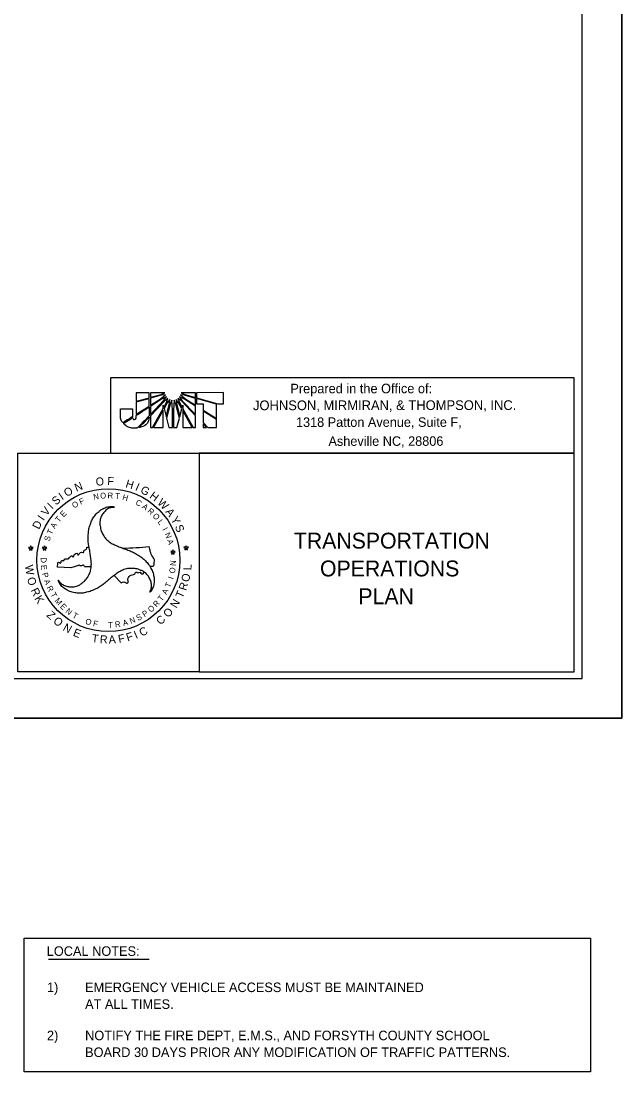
# Model space of a CAD drawing. Extents: x 762655 to 770567, y 650864 to 655190.
# Drawn here: x 765831 to 766209, y 652556 to 653217 of the extents above; entities that cross this region are included whole.
import ezdxf

# ---------------------------------------------------------------- set-up
doc = ezdxf.new("R2010")
doc.units = 0
for name, color, linetype in [('Default', 7, 'Continuous'), ('DEV BORDER CELL', 7, 'Continuous'), ('DEV DOT SWIRL SEAL CELL', 7, 'Continuous'), ('Scratch_Level_3', 7, 'Continuous'), ('Sheet Plan CELL', 7, 'Continuous'), ('Sheet Plot Border Outside CELL', 7, 'Continuous'), ('Sheet Title CELL', 7, 'Continuous'), ('Text', 7, 'Continuous')]:
    doc.layers.add(name, color=color, linetype=linetype)

msp = doc.modelspace()

# ---------------------------------------------------------------- linework, layer by layer
at = {"layer": 'Default'}
for p, q in [((765911.27, 652983.54), (765903.17, 652983.54)), ((765903.17, 652983.54), (765903.17, 652978.17)), ((765911.27, 652980.42), (765911.27, 652983.54)), ((765921.22, 652983.59), (765912.11, 652983.59)), ((765912.11, 652983.59), (765912.11, 652980.69)), ((765918.9, 652982.56), (765921.22, 652983.59)), ((765940.51, 652983.57), (765931.53, 652983.6)), ((765931.53, 652983.6), (765933.81, 652982.54)), ((765940.51, 652980.66), (765940.51, 652983.57)), ((765958.16, 652983.63), (765941.14, 652983.61)), ((765941.14, 652983.61), (765941.14, 652980.49)), ((765958.17, 652976.65), (765958.16, 652983.63)), ((765903.17, 652978.17), (765911.27, 652980.42)), ((765911.27, 652979.83), (765903.18, 652977.55)), ((765903.18, 652977.55), (765903.18, 652970)), ((765911.27, 652975.14), (765911.27, 652979.83)), ((765912.11, 652980.69), (765918.9, 652982.56)), ((765918.9, 652981.94), (765912.11, 652980.06)), ((765912.11, 652980.06), (765912.11, 652975.68)), ((765912.11, 652975.68), (765918.19, 652979.53)), ((765919.13, 652979.44), (765912.12, 652974.97)), ((765912.12, 652969.92), (765920.65, 652978.81)), ((765921, 652978.37), (765912.12, 652969.06)), ((765918.19, 652979.53), (765921.54, 652982.26)), ((765921.54, 652982.26), (765918.9, 652981.94)), ((765922.21, 652981), (765919.13, 652979.44)), ((765920.47, 652974.35), (765922.16, 652977.44)), ((765920.65, 652978.81), (765922.21, 652981)), ((765922.71, 652977.25), (765920.69, 652973.59)), ((765923.15, 652980.03), (765921, 652978.37)), ((765921.99, 652968.72), (765924.08, 652976.81)), ((765922.16, 652977.44), (765923.15, 652980.03)), ((765924.31, 652979.31), (765922.71, 652977.25)), ((765924.08, 652976.81), (765924.31, 652979.31)), ((765925.65, 652978.95), (765924.54, 652976.36)), ((765926, 652972.56), (765925.65, 652978.95)), ((765926.98, 652978.95), (765926.57, 652972.56)), ((765928.05, 652976.36), (765926.98, 652978.95)), ((765928.28, 652979.31), (765928.55, 652976.72)), ((765929.84, 652977.26), (765928.28, 652979.31)), ((765929.43, 652980.03), (765930.42, 652977.44)), ((765931.58, 652978.38), (765929.43, 652980.03)), ((765931.94, 652973.46), (765929.84, 652977.26)), ((765930.37, 652981.01), (765931.94, 652978.78)), ((765933.5, 652979.45), (765930.37, 652981.01)), ((765930.42, 652977.44), (765932.16, 652974.22)), ((765931.08, 652982.27), (765934.48, 652979.49)), ((765933.58, 652981.95), (765931.08, 652982.27)), ((765940.47, 652969.01), (765931.58, 652978.38)), ((765931.94, 652978.78), (765940.47, 652969.85)), ((765940.47, 652975.03), (765933.5, 652979.45)), ((765940.51, 652980.04), (765933.58, 652981.95)), ((765933.81, 652982.54), (765940.51, 652980.66)), ((765934.48, 652979.49), (765940.47, 652975.76)), ((765940.47, 652975.76), (765940.51, 652980.04)), ((765941.14, 652980.49), (765941.14, 652980.39)), ((765941.14, 652980.39), (765954.55, 652976.65)), ((765941.14, 652979.91), (765941.14, 652979.86)), ((765953.69, 652976.34), (765941.14, 652979.91)), ((765941.14, 652979.86), (765941.15, 652976.6)), ((765903.18, 652970), (765911.27, 652975.14)), ((765912.12, 652974.97), (765912.12, 652969.92)), ((765913.46, 652961.72), (765920.07, 652973.68)), ((765920.07, 652972.52), (765914.09, 652961.72)), ((765920.07, 652973.68), (765920.06, 652975.82)), ((765920.06, 652975.82), (765920.47, 652974.35)), ((765920.13, 652961.72), (765920.07, 652972.52)), ((765920.69, 652973.59), (765921.99, 652968.72)), ((765924.54, 652976.36), (765922.26, 652967.6)), ((765926.01, 652961.77), (765926, 652972.56)), ((765926.57, 652972.56), (765926.58, 652961.77)), ((765930.39, 652967.48), (765928.05, 652976.36)), ((765928.55, 652976.72), (765930.65, 652968.55)), ((765930.65, 652968.55), (765931.94, 652973.46)), ((765932.16, 652974.22), (765932.57, 652975.83)), ((765932.57, 652975.83), (765932.57, 652973.46)), ((765932.57, 652973.46), (765939.05, 652961.74)), ((765938.38, 652961.78), (765932.57, 652972.3)), ((765932.57, 652972.3), (765932.58, 652961.77)), ((765940.47, 652969.85), (765940.47, 652975.03)), ((765941.15, 652976.6), (765945.3, 652976.6)), ((765945.3, 652976.6), (765945.3, 652972.71)), ((765945.3, 652972.71), (765953.7, 652967.4)), ((765945.31, 652972.05), (765945.31, 652964.8)), ((765953.7, 652966.78), (765945.31, 652972.05)), ((765953.7, 652967.4), (765953.69, 652976.34)), ((765954.55, 652976.65), (765958.17, 652976.65)), ((765912.12, 652969.06), (765912.13, 652961.72)), ((765922.26, 652967.6), (765923.79, 652961.77)), ((765928.83, 652961.77), (765930.39, 652967.48)), ((765940.48, 652961.74), (765940.47, 652969.01)), ((765945.31, 652964.8), (765948.21, 652961.75)), ((765947.41, 652961.75), (765945.31, 652964.02)), ((765945.31, 652964.02), (765945.31, 652961.75)), ((765953.7, 652961.75), (765953.7, 652966.78)), ((765912.13, 652961.72), (765913.46, 652961.72)), ((765914.09, 652961.72), (765920.13, 652961.72)), ((765923.79, 652961.77), (765926.01, 652961.77)), ((765926.58, 652961.77), (765928.83, 652961.77)), ((765932.58, 652961.77), (765938.38, 652961.78)), ((765939.05, 652961.74), (765940.48, 652961.74)), ((765945.31, 652961.75), (765947.41, 652961.75)), ((765948.21, 652961.75), (765953.7, 652961.75)), ((765847.91, 652627.18), (765911.34, 652627.18))]:
    msp.add_line(p, q, dxfattribs=at)
for points in [[(765903.17, 652978.17), (765911.27, 652980.42), (765911.27, 652983.54), (765903.17, 652983.54), (765903.17, 652978.17)], [(765918.9, 652982.56), (765921.22, 652983.59), (765912.11, 652983.59), (765912.11, 652980.69), (765918.9, 652982.56)], [(765933.81, 652982.54), (765940.51, 652980.66), (765940.51, 652983.57), (765931.53, 652983.6), (765933.81, 652982.54)], [(765903.18, 652970), (765911.27, 652975.14), (765911.27, 652979.83), (765903.18, 652977.55), (765903.18, 652970)], [(765912.11, 652980.06), (765912.11, 652975.68), (765918.19, 652979.53), (765921.54, 652982.26), (765918.9, 652981.94), (765912.11, 652980.06)], [(765912.12, 652974.97), (765912.12, 652969.92), (765920.65, 652978.81), (765922.21, 652981), (765919.13, 652979.44), (765912.12, 652974.97)], [(765923.15, 652980.03), (765921, 652978.37), (765912.12, 652969.06), (765912.13, 652961.72), (765913.46, 652961.72), (765920.07, 652973.68), (765920.06, 652975.82), (765920.47, 652974.35), (765922.16, 652977.44), (765923.15, 652980.03)], [(765924.31, 652979.31), (765922.71, 652977.25), (765920.69, 652973.59), (765921.99, 652968.72), (765924.08, 652976.81), (765924.31, 652979.31)], [(765924.54, 652976.36), (765922.26, 652967.6), (765923.79, 652961.77), (765926.01, 652961.77), (765926, 652972.56), (765925.65, 652978.95), (765924.54, 652976.36)], [(765926.98, 652978.95), (765926.57, 652972.56), (765926.58, 652961.77), (765928.83, 652961.77), (765930.39, 652967.48), (765928.05, 652976.36), (765926.98, 652978.95)], [(765928.28, 652979.31), (765928.55, 652976.72), (765930.65, 652968.55), (765931.94, 652973.46), (765929.84, 652977.26), (765928.28, 652979.31)], [(765929.43, 652980.03), (765930.42, 652977.44), (765932.16, 652974.22), (765932.57, 652975.83), (765932.57, 652973.46), (765939.05, 652961.74), (765940.48, 652961.74), (765940.47, 652969.01), (765931.58, 652978.38), (765929.43, 652980.03)], [(765930.37, 652981.01), (765931.94, 652978.78), (765940.47, 652969.85), (765940.47, 652975.03), (765933.5, 652979.45), (765930.37, 652981.01)], [(765931.08, 652982.27), (765934.48, 652979.49), (765940.47, 652975.76), (765940.51, 652980.04), (765933.58, 652981.95), (765931.08, 652982.27)], [(765941.14, 652979.91), (765941.14, 652979.86), (765941.15, 652976.6), (765945.3, 652976.6), (765945.3, 652972.71), (765953.7, 652967.4), (765953.69, 652976.34), (765941.14, 652979.91)], [(765914.09, 652961.72), (765920.13, 652961.72), (765920.07, 652972.52), (765914.09, 652961.72)], [(765932.58, 652961.77), (765938.38, 652961.78), (765932.57, 652972.3), (765932.58, 652961.77)], [(765945.31, 652972.05), (765945.31, 652964.8), (765948.21, 652961.75), (765953.7, 652961.75), (765953.7, 652966.78), (765945.31, 652972.05), (765945.31, 652972.05)], [(765945.31, 652961.75), (765945.31, 652961.75), (765947.41, 652961.75), (765945.31, 652964.02), (765945.31, 652961.75)]]:
    msp.add_lwpolyline(points, dxfattribs=at)
for points in [[(765900.85, 652973.48), (765900.85, 652973.48), (765893.36, 652973.47), (765893.36, 652973.47), (765893.36, 652973.47), (765893.36, 652968.78), (765893.36, 652968.78), (765893.36, 652968.78), (765893.36, 652968.28), (765893.36, 652968.28), (765893.37, 652966.82), (765893.85, 652965.65), (765894.7, 652964.68), (765894.7, 652964.68), (765900.86, 652968.43), (765900.86, 652968.52), (765900.86, 652968.52), (765900.85, 652973.48), (765900.85, 652973.48)], [(765900.85, 652973.48), (765900.85, 652973.48), (765893.36, 652973.47), (765893.36, 652973.47), (765893.36, 652973.47), (765893.36, 652968.78), (765893.36, 652968.78), (765893.36, 652968.78), (765893.36, 652968.28), (765893.36, 652968.28), (765893.37, 652966.82), (765893.85, 652965.65), (765894.7, 652964.68), (765894.7, 652964.68), (765900.86, 652968.43), (765900.86, 652968.52), (765900.86, 652968.52), (765900.85, 652973.48), (765900.85, 652973.48)], [(765902.02, 652966.73), (765901.54, 652966.73), (765901.13, 652967), (765900.95, 652967.89), (765900.95, 652967.89), (765895.14, 652964.29), (765895.14, 652964.29), (765896.94, 652962.41), (765899.8, 652961.29), (765902.21, 652961.29), (765902.84, 652961.29), (765903.32, 652961.35), (765903.99, 652961.48), (765903.99, 652961.48), (765911.28, 652969.02), (765911.28, 652969.02), (765911.28, 652969.02), (765911.27, 652974.47), (765911.27, 652974.47), (765911.27, 652974.47), (765903.18, 652969.32), (765903.18, 652969.32), (765903.18, 652967.28), (765902.69, 652966.73), (765902.02, 652966.73)], [(765902.02, 652966.73), (765901.54, 652966.73), (765901.13, 652967), (765900.95, 652967.89), (765900.95, 652967.89), (765895.14, 652964.29), (765895.14, 652964.29), (765896.94, 652962.41), (765899.8, 652961.29), (765902.21, 652961.29), (765902.84, 652961.29), (765903.32, 652961.35), (765903.99, 652961.48), (765903.99, 652961.48), (765911.28, 652969.02), (765911.28, 652969.02), (765911.28, 652969.02), (765911.27, 652974.47), (765911.27, 652974.47), (765911.27, 652974.47), (765903.18, 652969.32), (765903.18, 652969.32), (765903.18, 652967.28), (765902.69, 652966.73), (765902.02, 652966.73)], [(765911.28, 652968.17), (765911.28, 652968.17), (765904.98, 652961.66), (765904.98, 652961.66), (765908.07, 652962.42), (765911.14, 652964.47), (765911.28, 652968.17)], [(765911.28, 652968.17), (765911.28, 652968.17), (765904.98, 652961.66), (765904.98, 652961.66), (765908.07, 652962.42), (765911.14, 652964.47), (765911.28, 652968.17)]]:
    msp.add_open_spline(points, degree=3, dxfattribs=at)
at = {"layer": 'DEV BORDER CELL'}
for points in [[(766183.85, 653853.76), (764683.84, 653853.76), (764683.84, 652803.75), (766183.85, 652803.75)], [(765828.7, 652945.52), (765942.7, 652945.52), (765942.7, 652808.02), (765828.7, 652808.02)], [(766178.7, 652945.52), (765942.7, 652945.52), (765942.7, 652808.02), (766178.7, 652808.02)]]:
    msp.add_lwpolyline(points, close=True, dxfattribs=at)
at = {"layer": 'DEV DOT SWIRL SEAL CELL'}
for p, q in [((765835.43, 652886.19), (765836.31, 652885.54)), ((765836.51, 652886.19), (765835.43, 652886.19)), ((765836.31, 652885.54), (765835.99, 652884.5)), ((765835.99, 652884.5), (765836.83, 652885.14)), ((765836.83, 652887.19), (765836.51, 652886.19)), ((765837.19, 652886.19), (765836.83, 652887.19)), ((765836.83, 652885.14), (765837.72, 652884.5)), ((765836.83, 652885.14), (765837.71, 652884.5)), ((765838.27, 652886.19), (765837.19, 652886.19)), ((765837.39, 652885.54), (765838.28, 652886.19)), ((765837.39, 652885.54), (765838.27, 652886.19)), ((765837.72, 652884.5), (765837.39, 652885.54)), ((765837.71, 652884.5), (765837.39, 652885.54)), ((765845.19, 652886.17), (765844.1, 652886.17)), ((765844.1, 652886.17), (765844.99, 652885.53)), ((765844.99, 652885.53), (765844.67, 652884.49)), ((765844.67, 652884.49), (765845.51, 652885.13)), ((765845.51, 652887.18), (765845.19, 652886.17)), ((765845.87, 652886.17), (765845.51, 652887.18)), ((765845.51, 652885.13), (765846.39, 652884.49)), ((765846.95, 652886.17), (765845.87, 652886.17)), ((765846.07, 652885.53), (765846.95, 652886.17)), ((765846.39, 652884.49), (765846.07, 652885.53)), ((765926.28, 652884.69), (765925.96, 652883.68)), ((765926.64, 652883.68), (765926.28, 652884.69)), ((765934.23, 652886.33), (765933.15, 652886.33)), ((765933.15, 652886.33), (765934.03, 652885.68)), ((765934.03, 652885.68), (765933.71, 652884.64)), ((765933.71, 652884.64), (765934.55, 652885.28)), ((765934.55, 652887.33), (765934.23, 652886.33)), ((765934.92, 652886.33), (765934.55, 652887.33)), ((765934.55, 652885.28), (765935.44, 652884.64)), ((765936, 652886.33), (765934.92, 652886.33)), ((765935.12, 652885.68), (765936, 652886.33)), ((765935.44, 652884.64), (765935.12, 652885.68)), ((765925.96, 652883.68), (765924.87, 652883.68)), ((765924.87, 652883.68), (765925.75, 652883.04)), ((765925.75, 652883.04), (765925.43, 652882)), ((765925.43, 652882), (765926.28, 652882.64)), ((765926.28, 652882.64), (765927.16, 652882)), ((765927.72, 652883.68), (765926.64, 652883.68)), ((765926.84, 652883.04), (765927.72, 652883.68)), ((765927.16, 652882), (765926.84, 652883.04)), ((765853.75, 652873.74), (765853.84, 652876.4)), ((765862.14, 652873.43), (765853.75, 652873.74)), ((765866.95, 652874.84), (765862.14, 652873.43)), ((765870.65, 652874.28), (765874.86, 652874.24)), ((765889.4, 652868.66), (765893.71, 652863.99))]:
    msp.add_line(p, q, dxfattribs=at)
for start, end in [(265.67849, 265.97623), (271.20351, 275.32356)]:
    msp.add_arc((765889.79, 653118.92), 233.19, start, end, dxfattribs=at)
for points in [[(765854.16, 652865.63), (765855.91, 652863.62), (765858.08, 652862.22), (765860.58, 652861.58), (765863.4, 652861.41), (765866.27, 652862.09), (765868.18, 652863.05), (765868.98, 652863.7), (765870.38, 652864.8), (765871.37, 652865.87), (765873.03, 652868.23), (765874.32, 652871.03), (765874.86, 652874.22), (765874.89, 652874.49), (765874.86, 652877.49), (765874.46, 652880.53), (765874.03, 652883.45), (765873.49, 652886.49), (765873.01, 652889.49), (765872.95, 652892.42), (765873.14, 652895.78), (765873.63, 652898.65), (765874.57, 652901.6), (765875.08, 652903), (765875.77, 652904.13), (765877.52, 652906.78), (765879.8, 652908.93), (765881.3, 652910.06), (765882.73, 652910.81), (765882.97, 652910.94), (765885.81, 652911.85), (765888.6, 652911.96), (765889.55, 652911.72)], [(765889.62, 652911.8), (765889.55, 652911.72), (765886.97, 652911.24), (765884.63, 652910.03), (765882.83, 652908.21), (765881.3, 652905.87), (765880.44, 652903.02), (765880.31, 652900.9), (765880.5, 652899.88), (765880.74, 652898.11), (765881.14, 652896.72), (765882.4, 652894.11), (765884.15, 652891.59), (765886.67, 652889.52), (765886.89, 652889.36), (765889.46, 652887.88), (765892.34, 652886.7), (765895.07, 652885.63), (765897.95, 652884.58), (765900.79, 652883.45), (765903.37, 652882.06), (765906.19, 652880.23), (765908.41, 652878.38), (765910.51, 652876.1), (765911.48, 652874.94), (765912.09, 652873.77), (765913.54, 652870.94), (765914.24, 652867.88), (765914.48, 652866.01), (765914.43, 652864.39), (765914.43, 652864.13), (765913.76, 652861.2), (765912.44, 652858.73), (765911.8, 652858.06)], [(765853.84, 652876.4), (765853.75, 652876.65), (765854.2, 652876.93), (765855.45, 652876.42), (765856.07, 652876.96), (765856.04, 652877.5), (765856.55, 652878.04), (765857.4, 652877.87), (765858.16, 652878.83), (765858.86, 652879.03), (765860.36, 652879.03), (765862.14, 652880.8), (765862.88, 652880.92), (765863.08, 652880.44), (765863.53, 652880.35), (765864.32, 652881.82), (765864.52, 652882.02), (765865.87, 652882.58), (765866.24, 652882.3), (765866.35, 652881.65), (765866.55, 652881.54), (765867, 652881.85), (765867.62, 652882.64), (765868.75, 652883.24), (765870.05, 652883.07), (765870.28, 652884.14), (765871.81, 652885.16), (765872.12, 652885.78), (765872.2, 652886.4)], [(765911.73, 652874.51), (765914.19, 652874.81), (765914.56, 652876.77), (765914.59, 652878.4), (765913.57, 652880.3), (765912.05, 652883.77), (765911.42, 652886.74)], [(765911.8, 652858.06), (765912.66, 652860.53), (765912.79, 652863.13), (765912.09, 652865.63), (765910.83, 652868.12), (765908.82, 652870.27), (765907.05, 652871.45), (765906.05, 652871.8), (765904.44, 652872.5), (765902.97, 652872.82), (765900.12, 652873.06), (765897.03, 652872.8), (765894, 652871.64), (765893.76, 652871.53), (765891.18, 652870.01), (765888.74, 652868.15), (765886.4, 652866.33), (765884.07, 652864.34), (765881.68, 652862.41), (765879.18, 652860.9), (765876.18, 652859.37), (765873.46, 652858.38), (765870.46, 652857.71), (765868.95, 652857.44), (765867.64, 652857.5), (765864.5, 652857.66), (765861.47, 652858.57), (765859.75, 652859.3), (765858.38, 652860.18), (765858.14, 652860.31), (765855.93, 652862.33), (765854.46, 652864.69), (765854.16, 652865.63)], [(765870.65, 652874.28), (765870.31, 652874.93), (765869.63, 652875.13), (765868.7, 652874.65), (765868.02, 652874.67), (765867.26, 652875.24), (765866.95, 652874.84)], [(765893.71, 652863.99), (765895.4, 652864.5), (765896.81, 652863.96), (765897.49, 652863.85), (765898.06, 652864.27), (765897.89, 652866.4), (765898.37, 652867.38), (765900.66, 652869.08), (765902.07, 652869.39), (765903.12, 652870.69), (765903.54, 652870.66), (765904.19, 652870.29), (765905.63, 652870.58), (765906.79, 652869.64), (765907.47, 652869.7), (765908.01, 652870.76)]]:
    msp.add_spline(points, degree=3, dxfattribs=at)
at = {"layer": 'Scratch_Level_3'}
msp.add_lwpolyline([(764520.84, 653878.75), (766208.85, 653878.75), (766208.85, 652778.75), (764520.84, 652778.75)], close=True, dxfattribs=at)
at = {"layer": 'Sheet Plan CELL'}
msp.add_lwpolyline([(766178.7, 652993.04), (765887.02, 652993.04), (765887.02, 652945.52), (766178.7, 652945.52)], close=True, dxfattribs=at)
at = {"layer": 'Sheet Plot Border Outside CELL'}
msp.add_lwpolyline([(764520.85, 652778.75), (766208.85, 652778.75), (766208.85, 653878.75), (764520.85, 653878.75)], close=True, dxfattribs=at)
at = {"layer": 'Text'}
msp.add_lwpolyline([(765832.71, 652640.4), (766189.14, 652640.4), (766189.14, 652556.18), (765832.71, 652556.18)], close=True, dxfattribs=at)
msp.add_circle((765885.7, 652878.23), 44.97, dxfattribs=at)

# ---------------------------------------------------------------- texts
at = {"layer": 'Default'}
for s, p in [('TRANSPORTATION ', (766002.37, 652885.5)), ('OPERATIONS', (766018.83, 652868)), ('PLAN', (766043, 652850.5))]:
    msp.add_text(s, height=10, dxfattribs=at).set_placement(p)
at = {"layer": 'DEV DOT SWIRL SEAL CELL'}
for s, height, rotation, p in [('F', 5.04, 357.25753, (765884.91, 652925.51)), ('O', 5.04, 30.09348, (765859.44, 652917.85)), ('N', 5.04, 21.58606, (765865.55, 652921.23)), ('O', 5.04, 5.76495, (765877.95, 652924.96)), ('H', 5.04, 343.45399, (765896.14, 652924.22)), ('I', 5.04, 335.80403, (765902.13, 652922.35)), ('G', 5.04, 331.5167, (765905.37, 652920.96)), ('S', 5.04, 40.58484, (765852.7, 652912.51)), ('I', 5.04, 34.38082, (765856.57, 652915.82)), ('F', 3.63, 24.25691, (765868.25, 652913.05)), ('N', 3.63, 9.02265, (765876.47, 652916.17)), ('O', 3.63, 3.94457, (765880.62, 652916.89)), ('R', 3.63, 358.86648, (765885.1, 652917.17)), ('H', 3.63, 343.63223, (765894.17, 652916.3)), ('H', 5.04, 323.46323, (765911.12, 652917.71)), ('W', 5.04, 315.81328, (765916.11, 652913.91)), ('V', 5.04, 51.5806, (765846.81, 652905.69)), ('I', 5.04, 44.87218, (765850.25, 652909.99)), ('O', 3.63, 29.33499, (765864.04, 652910.7)), ('C', 3.63, 333.47606, (765902.41, 652913.39)), ('A', 3.63, 323.31989, (765906.5, 652911.26)), ('R', 3.63, 318.24181, (765910, 652908.71)), ('I', 5.04, 55.86794, (765844.88, 652902.74)), ('T', 3.63, 49.64733, (765854.57, 652901.71)), ('E', 3.63, 44.56924, (765857.43, 652905.02)), ('O', 3.63, 313.16372, (765913.21, 652905.79)), ('L', 3.63, 308.08564, (765916.42, 652902.12)), ('A', 5.04, 306.77624, (765921.3, 652908.61)), ('Y', 5.04, 299.74838, (765924.71, 652903.97)), ('D', 5.04, 63.45904, (765842.02, 652897.21)), ('T', 3.63, 64.88158, (765850.08, 652893.93)), ('A', 3.63, 59.8035, (765852.01, 652897.72)), ('I', 3.63, 297.92947, (765919.47, 652897.61)), ('S', 5.04, 293.2249, (765927.35, 652899.31)), ('S', 3.63, 69.95967, (765848.49, 652889.79)), ('N', 3.63, 292.85138, (765920.99, 652894.71)), ('A', 3.63, 287.7733, (765922.58, 652890.65)), ('D', 3.63, 270.27201, (765843.14, 652879.93)), ('N', 3.63, 87.73296, (765928.14, 652874.57)), ('E', 3.63, 275.35009, (765843.26, 652875.07)), ('O', 3.63, 82.92689, (765927.51, 652869.7)), ('P', 3.63, 285.50626, (765843.86, 652869.87)), ('A', 3.63, 290.58434, (765845.06, 652865.41)), ('T', 3.63, 67.69263, (765924.43, 652860.55)), ('I', 3.63, 72.77072, (765926.43, 652865.94)), ('R', 3.63, 295.66243, (765846.74, 652861.07)), ('T', 3.63, 300.74051, (765849.02, 652856.67)), ('A', 3.63, 62.61455, (765922.2, 652856.21)), ('M', 3.63, 310.89668, (765851.63, 652852.57)), ('R', 3.63, 47.38029, (765916, 652848.33)), ('T', 3.63, 52.45838, (765919.25, 652852.07)), ('E', 3.63, 315.97477, (765854.97, 652848.75)), ('N', 3.63, 321.05285, (765858.39, 652845.59)), ('T', 3.63, 331.20902, (765862.64, 652842.35)), ('P', 3.63, 32.14604, (765908.39, 652842.24)), ('O', 3.63, 42.30221, (765912.47, 652845.07)), ('O', 3.63, 341.36519, (765870.85, 652838.33)), ('F', 3.63, 346.44327, (765875.77, 652836.86)), ('T', 3.63, 1.67753, (765885.53, 652835.66)), ('R', 3.63, 6.75561, (765890.02, 652835.9)), ('A', 3.63, 16.91178, (765895.28, 652836.67)), ('N', 3.63, 21.98987, (765899.85, 652838.06)), ('S', 3.63, 27.06795, (765904.27, 652839.94))]:
    msp.add_text(s, height=height, rotation=rotation, dxfattribs=at).set_placement(p)
at = {"layer": 'Sheet Title CELL'}
for s, height, p in [('Prepared in the Office of:', 5.9987, (766000.19, 652983.19)), ('JOHNSON, MIRMIRAN, & THOMPSON, INC.', 6.0929, (765976.67, 652972.59)), ('1318 Patton Avenue, Suite F,', 5.9679, (766003.72, 652962.04)), ('Asheville NC, 28806', 5.9679, (766024.17, 652950.12))]:
    msp.add_text(s, height=height, rotation=0.05163, dxfattribs=at).set_placement(p)
at = {"layer": 'Text'}
for s, height, rotation, p in [('T', 3.63, 353.7884, (765889.73, 652916.94)), ('W', 5.04, 278.14998, (765833.21, 652874.86)), ('L', 5.04, 87.42899, (765937.89, 652871.78)), ('O', 5.04, 287.11471, (765834.38, 652866.72)), ('O', 5.04, 78.98964, (765936.38, 652864.19)), ('R', 5.04, 295.55406, (765836.62, 652859.31)), ('T', 5.04, 66.88101, (765932.31, 652853.87)), ('R', 5.04, 72.75186, (765934.56, 652858.76)), ('K', 5.04, 301.79184, (765838.97, 652854.09)), ('N', 5.04, 58.89198, (765928.47, 652847.63)), ('Z', 5.04, 316.16875, (765846.43, 652843.24)), ('O', 5.04, 50.45263, (765923.52, 652841.68)), ('O', 5.04, 322.52328, (765850.54, 652839.11)), ('N', 5.04, 330.96263, (765856.66, 652834.38)), ('C', 5.04, 43.08071, (765918.51, 652837.13)), ('E', 5.04, 338.95166, (765863.04, 652830.77)), ('T', 5.04, 352.69479, (765874.96, 652826.74)), ('F', 5.04, 11.77506, (765892.38, 652826.06)), ('F', 5.04, 17.76266, (765897.79, 652827.04)), ('I', 5.04, 23.75026, (765903.06, 652828.58)), ('C', 5.04, 28.0033, (765906.69, 652830.01)), ('R', 5.04, 358.56564, (765880.28, 652825.91)), ('A', 5.04, 4.80342, (765886, 652825.63))]:
    msp.add_text(s, height=height, rotation=rotation, dxfattribs=at).set_placement(p)
for s, p in [('LOCAL NOTES:', (765846.91, 652629.25)), ('1)', (765847.03, 652606.45)), ('EMERGENCY VEHICLE ACCESS MUST BE MAINTAINED', (765871.03, 652606.45)), ('AT ALL TIMES.', (765871.03, 652595.9)), ('2)', (765847.03, 652576.16)), ('NOTIFY THE FIRE DEPT, E.M.S., AND FORSYTH COUNTY SCHOOL ', (765871.03, 652576.16)), ('BOARD 30 DAYS PRIOR ANY MODIFICATION OF TRAFFIC PATTERNS.', (765871.03, 652565.61))]:
    msp.add_text(s, height=6, dxfattribs=at).set_placement(p)

doc.saveas('drawing.dxf')
